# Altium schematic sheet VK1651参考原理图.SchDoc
size A4
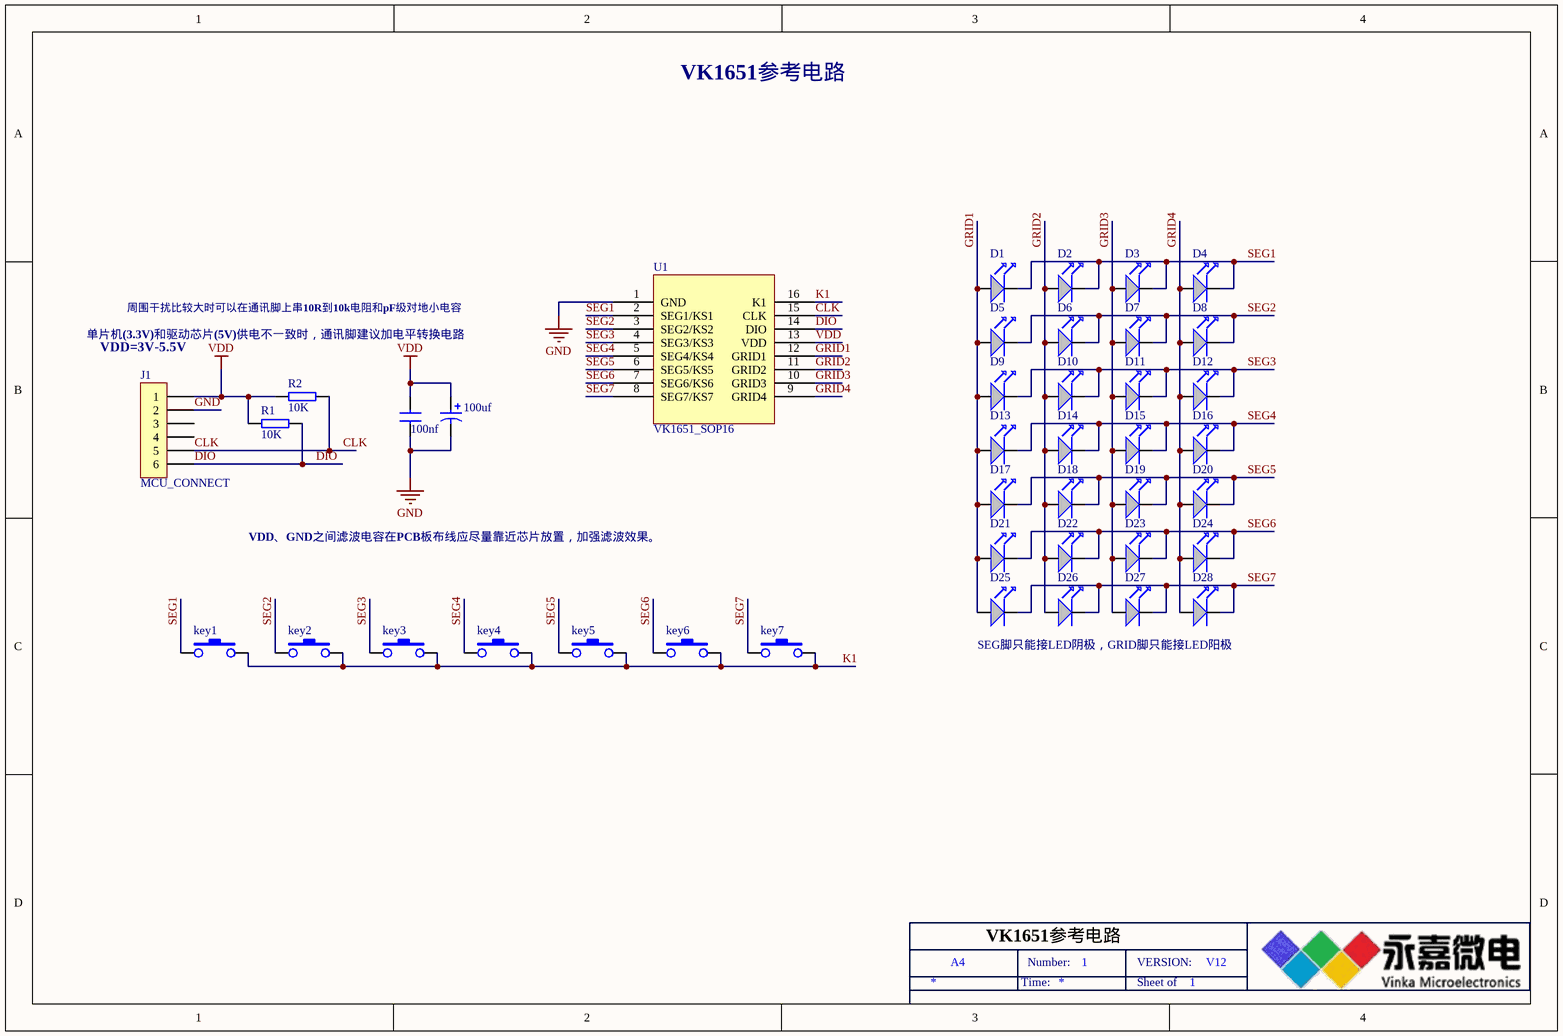
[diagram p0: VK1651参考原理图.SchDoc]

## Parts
100nf  CAP  (value not drawn)
100uf  CAP2  (value not drawn)
D1  (no value)  [1206-LED]
D2  (no value)  [1206-LED]
D3  (no value)  [1206-LED]
D4  (no value)  [1206-LED]
D5  (no value)  [1206-LED]
D6  (no value)  [1206-LED]
D7  (no value)  [1206-LED]
D8  (no value)  [1206-LED]
D9  (no value)  [1206-LED]
D10  (no value)  [1206-LED]
D11  (no value)  [1206-LED]
D12  (no value)  [1206-LED]
D13  (no value)  [1206-LED]
D14  (no value)  [1206-LED]
D15  (no value)  [1206-LED]
D16  (no value)  [1206-LED]
D17  (no value)  [1206-LED]
D18  (no value)  [1206-LED]
D19  (no value)  [1206-LED]
D20  (no value)  [1206-LED]
D21  (no value)  [1206-LED]
D22  (no value)  [1206-LED]
D23  (no value)  [1206-LED]
D24  (no value)  [1206-LED]
D25  (no value)  [1206-LED]
D26  (no value)  [1206-LED]
D27  (no value)  [1206-LED]
D28  (no value)  [1206-LED]
J1  MCU_CONNECT
key1  KEY  [AN12]  (value not drawn)
key2  KEY  [AN12]  (value not drawn)
key3  KEY  [AN12]  (value not drawn)
key4  KEY  [AN12]  (value not drawn)
key5  KEY  [AN12]  (value not drawn)
key6  KEY  [AN12]  (value not drawn)
key7  KEY  [AN12]  (value not drawn)
R1  10K  [0603-R]
R2  10K  [0603-R]
U1  VK1651_SOP16

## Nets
GND: 100nf.2 100uf.2 J1.2 U1.1(GND)
VDD: 100nf.1 100uf.1 J1.1 R1.1 R2.1 U1.13(VDD)
CLK: J1.5 R2.2 U1.15(CLK)
DIO: J1.6 R1.2 U1.14(DIO)
GRID1: D1.1 D5.1 D9.1 D13.1 D17.1 D21.1 D25.1 U1.12(GRID1)
GRID2: D2.1 D6.1 D10.1 D14.1 D18.1 D22.1 D26.1 U1.11(GRID2)
GRID3: D3.1 D7.1 D11.1 D15.1 D19.1 D23.1 D27.1 U1.10(GRID3)
GRID4: D4.1 D8.1 D12.1 D16.1 D20.1 D24.1 D28.1 U1.9(GRID4)
K1: key1.2 key2.2 key3.2 key4.2 key5.2 key6.2 key7.2 U1.16(K1)
SEG1: D1.2 D2.2 D3.2 D4.2 key1.1 U1.2(SEG1/KS1)
SEG2: D5.2 D6.2 D7.2 D8.2 key2.1 U1.3(SEG2/KS2)
SEG3: D9.2 D10.2 D11.2 D12.2 key3.1 U1.4(SEG3/KS3)
SEG4: D13.2 D14.2 D15.2 D16.2 key4.1 U1.5(SEG4/KS4)
SEG5: D17.2 D18.2 D19.2 D20.2 key5.1 U1.6(SEG5/KS5)
SEG6: D21.2 D22.2 D23.2 D24.2 key6.1 U1.7(SEG6/KS6)
SEG7: D25.2 D26.2 D27.2 D28.2 key7.1 U1.8(SEG7/KS7)

Not connected (* = marked no-connect by the designer): J1 3 4

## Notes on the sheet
- VK1651参考电路
- 周围干扰比较大时可以在通讯脚上串10R到10k电阻和pF级对地小电容
- 单片机(3.3V)和驱动芯片(5V)供电不一致时，通讯脚建议加电平转换电路
- (near J1) VDD=3V-5.5V
- VDD、GND之间滤波电容在PCB板布线应尽量靠近芯片放置，加强滤波效果。
- SEG脚只能接LED阴极，GRID脚只能接LED阳极
- A4
- Time:
- Number:
- 1
- Sheet of
- VERSION:
- V12

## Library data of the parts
100nf = CAP: Capacitor
100uf = CAP2: Bi-Polar Capacitor
D1-D28 = LED: Text Field1: 30; Text Field2: 20
J1 = CON6: Connector
R1 R2 = RES: Resistor
U1 = VK1651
